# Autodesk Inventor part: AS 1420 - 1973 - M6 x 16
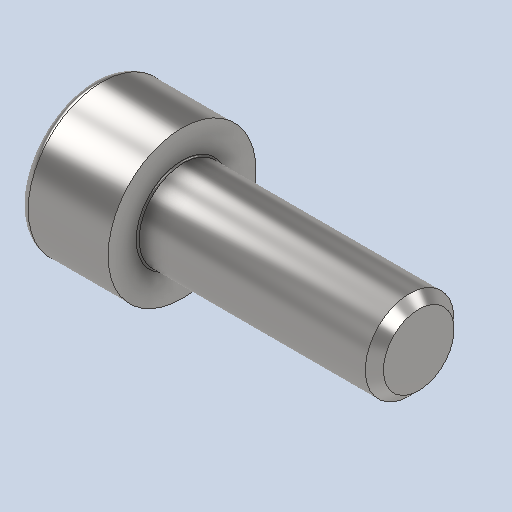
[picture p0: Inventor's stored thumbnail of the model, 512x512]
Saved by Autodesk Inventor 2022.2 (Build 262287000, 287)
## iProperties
Created: 2024-01
Part Number: AS 1420 - 1973 - M6 x 16
Material: Acciaio, Dolce
Document SubType Name: Modeling
Designer: 18907419
Density: 7.85 g/cm^3
Appearance: Default
Author: 18907419
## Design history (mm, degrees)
feature "Solid1"
node "Solido1"
